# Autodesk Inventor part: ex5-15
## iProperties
Shininess: 64.0
Length Units: 11272
Angle Units: 11279
Time Units: 11290
Mass Units: 11286
Length Display Precision: 3
Angle Display Precision: 2
Compacted: True
Part Number: ex5-15
Document SubType Name: Modeling
Created: 2002-09
Designer: Elise Moss
Density: 0.0
Volumn: 0.0
Area: 0.0
PropertySet Name: Model Information
Control State: 0
Master: False
Checked Out: False
Author: Elise Moss
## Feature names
1. Revolution1
2. Hole1
3. Shell1
4. Loft1
5. Sweep1
6. Coil1
7. Fillet1
8. Rib Chamfer [Chamfer]
